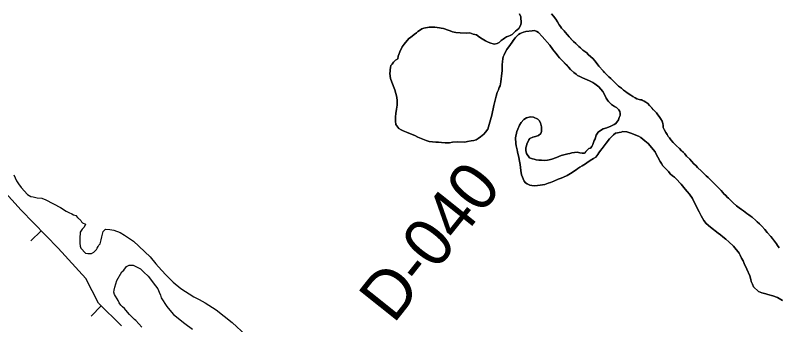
# Model space of a CAD drawing. Extents: x 3187622 to 3225504, y 800805 to 826213.
# Drawn here: x 3200621 to 3201935, y 813444 to 813977 of the extents above; entities that cross this region are included whole.
import ezdxf

# ---------------------------------------------------------------- set-up
doc = ezdxf.new("R2010")
doc.units = 0
for name, color, linetype in [('V-BORW-LINE', 7, 'Continuous'), ('V-RIVR-RANG-IDEN', 7, 'Continuous'), ('V-SITE-VEGE', 7, 'Continuous'), ('V-TOPO-SHOR', 7, 'Continuous')]:
    doc.layers.add(name, color=color, linetype=linetype)

msp = doc.modelspace()

# ---------------------------------------------------------------- linework, layer by layer
at = {"layer": 'V-BORW-LINE'}
for p, q in [((3200666.2, 813605.5), (3200648.2, 813588.1)), ((3200769.5, 813476.4), (3200751.9, 813458.6))]:
    msp.add_line(p, q, dxfattribs=at)
msp.add_lwpolyline([(3200804, 813442.2), (3200764.8, 813481), (3200742.7, 813523.6), (3200695, 813575.6), (3200631.7, 813641.3), (3200561.3, 813717.8), (3200477.3, 813821.7), (3200403.7, 813913.7), (3200338.8, 813979.6), (3200261.2, 814079.8), (3200192.3, 814157.6), (3200164.5, 814198.8), (3200123.2, 814226.2), (3200093.6, 814225.8), (3200067.7, 814233), (3200052.4, 814253), (3200045.7, 814270.2), (3200039.4, 814293.2), (3200029.7, 814306.3)], dxfattribs=at)
at = {"layer": 'V-SITE-VEGE'}
for points in [[(3201267.4, 813867.7), (3201266.5, 813871.7), (3201266.3, 813876.7), (3201266.4, 813879.7), (3201266.4, 813882.7), (3201267, 813886.9), (3201267.8, 813889.9), (3201269.9, 813892.4), (3201272.2, 813895.9), (3201276, 813899.3), (3201279.6, 813901.7), (3201280.7, 813906), (3201281.5, 813909.2), (3201283.1, 813913.9), (3201287.5, 813922.4), (3201290.6, 813927.1), (3201292.9, 813930), (3201296.5, 813934), (3201299, 813936.4), (3201301.6, 813938.6), (3201307.7, 813943.5), (3201312, 813946.4), (3201314.3, 813948.7), (3201316.9, 813950.6), (3201321.2, 813953.5), (3201324.4, 813954.7), (3201333.7, 813956), (3201343.5, 813955.9), (3201351.3, 813955.2), (3201354.5, 813954.6), (3201358.7, 813953.6), (3201366.4, 813950.9), (3201369.7, 813949.6), (3201374.2, 813948.2), (3201379.7, 813947.1), (3201387.4, 813946.5), (3201397.4, 813946), (3201403.7, 813946.2), (3201409.6, 813944.1), (3201415.1, 813942.9), (3201420.6, 813938.8), (3201424.8, 813936), (3201430.7, 813932.9), (3201434.4, 813930.8), (3201438.4, 813929), (3201445.4, 813927.1), (3201450.9, 813928), (3201454.2, 813929.7), (3201458, 813933.1), (3201461.1, 813935.3), (3201463.4, 813937.3), (3201466.9, 813939.7), (3201470.4, 813940.4), (3201473.2, 813941.6), (3201476.8, 813943.8), (3201482.6, 813949.2), (3201488, 813954.1), (3201490.8, 813958.8), (3201492.2, 813963), (3201491.4, 813974), (3201489.5, 813979.3)], [(3201544.1, 813979.3), (3201548, 813974.9), (3201551.7, 813970.1), (3201554.6, 813965.6), (3201557.5, 813960), (3201559.7, 813957.2), (3201561.6, 813954.6), (3201566, 813949.8), (3201568, 813947.3), (3201571.9, 813942.9), (3201574.6, 813939.4), (3201582.2, 813931.5), (3201586.2, 813927.9), (3201591.3, 813923), (3201594, 813920.7), (3201598.5, 813916.6), (3201601.9, 813914), (3201604.9, 813911.7), (3201607.6, 813909.2), (3201616, 813901.5), (3201619.2, 813898.2), (3201621.1, 813895.4), (3201625.7, 813889), (3201633.1, 813880.9), (3201639.2, 813874.5), (3201643.2, 813870.7), (3201646.4, 813867.9), (3201653.5, 813860.7), (3201659.9, 813854.8), (3201664.6, 813851), (3201668.3, 813847.6), (3201671.7, 813845.3), (3201674.7, 813843.3), (3201681.1, 813838.9), (3201684.1, 813836.8), (3201688.3, 813834.2), (3201691.5, 813832.7), (3201695.5, 813831.8), (3201699.8, 813830.7)], [(3201640.6, 813830.6), (3201638.7, 813833.7), (3201636.8, 813837.7), (3201632.7, 813845.3), (3201626, 813853.2), (3201619.1, 813858.4), (3201615.4, 813860.7), (3201609.5, 813863.8), (3201602, 813867), (3201597.6, 813869), (3201593.3, 813871.4), (3201589.1, 813873.2), (3201586.6, 813875), (3201582.9, 813878.1), (3201577.3, 813883.5), (3201573.6, 813887.5), (3201558.1, 813903.6), (3201555.5, 813906.9), (3201552.3, 813910.7), (3201548.6, 813915.3), (3201546.9, 813917.9), (3201541.5, 813925.2), (3201528.3, 813939.8), (3201521.7, 813946.7), (3201519.2, 813948.7), (3201515.2, 813950.3), (3201511.2, 813950.1), (3201500.2, 813948.6), (3201495.9, 813947.4), (3201490.3, 813945), (3201487.8, 813943.3), (3201485, 813941.1), (3201482.4, 813938.6), (3201480.6, 813935.9), (3201476.5, 813930.5), (3201473.9, 813926.5), (3201467.7, 813917.6), (3201464.6, 813912.4), (3201462.8, 813908.7), (3201461, 813905.2), (3201460.4, 813902.2), (3201460.1, 813896.7), (3201459.7, 813892), (3201459.3, 813881.7), (3201458.3, 813871.7), (3201457.8, 813867.2), (3201457.2, 813862), (3201456.3, 813858.5), (3201455.8, 813855.3), (3201454.5, 813852.3), (3201453.1, 813848.5), (3201451, 813843.6), (3201448.9, 813837.1), (3201447.5, 813830.4), (3201445.3, 813821.4), (3201444, 813815.4), (3201442.9, 813810.4), (3201441.8, 813804.7), (3201437.2, 813788.5), (3201434.8, 813780.8), (3201430.7, 813775.1), (3201428.1, 813772.1), (3201425.3, 813769.4), (3201422, 813767.5), (3201418.2, 813764.6), (3201414.7, 813762.4), (3201410.6, 813761.2), (3201406.3, 813760.3), (3201399.8, 813759.2), (3201395.3, 813758.2), (3201382.3, 813758.5), (3201374, 813758.1), (3201368.7, 813757.2), (3201361.5, 813757.1), (3201355.2, 813757.8), (3201350, 813758.4), (3201345.2, 813758.2), (3201333.7, 813759.4), (3201328.7, 813761), (3201322.8, 813763.4), (3201314.3, 813766.8), (3201309.3, 813769.4), (3201304.4, 813771.5), (3201294.9, 813775.2), (3201289.2, 813777.8), (3201285.7, 813779.4), (3201281.8, 813781.7), (3201279.6, 813783.8), (3201276.7, 813788.6), (3201276, 813794.1), (3201275.8, 813798.6), (3201275.9, 813801.9), (3201276.5, 813807.4), (3201277.4, 813815.1), (3201278.5, 813821.9), (3201278.7, 813829.6), (3201278.1, 813835.9), (3201276.4, 813841.7), (3201274.8, 813848), (3201269.8, 813861.3), (3201267.4, 813867.7)], [(3201589.8, 813712.7), (3201586.7, 813710.5), (3201577.3, 813704.1), (3201571.3, 813700.5), (3201564.9, 813697.9), (3201561.2, 813696.4), (3201555.9, 813694.5), (3201548.3, 813691.2), (3201542.7, 813688.8), (3201538.9, 813687.3), (3201532.6, 813685.5), (3201528.9, 813684.5), (3201524.6, 813683.9), (3201515.8, 813682.8), (3201510.6, 813683.4), (3201507.1, 813684.2), (3201502.4, 813686.3), (3201499.6, 813688.1), (3201497.4, 813690.9), (3201492.9, 813701.8), (3201491.5, 813709.3), (3201490.2, 813719.6), (3201489.1, 813725.6), (3201488, 813731.9), (3201485.9, 813741.5), (3201485, 813745.2), (3201483.6, 813751.8), (3201482.9, 813755.8), (3201482.6, 813765.6), (3201484.8, 813776.8), (3201486.4, 813780.8), (3201489.5, 813787.2), (3201491.9, 813791.9), (3201496.7, 813797.1), (3201501.5, 813799.8), (3201505.8, 813801.4), (3201508.8, 813801.6), (3201513.3, 813801.3), (3201520.8, 813797.9), (3201523.2, 813795.6), (3201525.7, 813791.3), (3201527.3, 813784.7), (3201527.4, 813776.7), (3201525.8, 813773), (3201522.2, 813769.8), (3201516.7, 813767.7), (3201512.2, 813766.7), (3201507.1, 813764.6), (3201505.1, 813762.1), (3201501.9, 813754.9), (3201501.1, 813751.9), (3201500, 813748.2), (3201500, 813743.9), (3201501.1, 813738.7), (3201506.7, 813731.3), (3201511.7, 813729.7), (3201514.7, 813728.6), (3201517.7, 813727.6), (3201522.4, 813727.2), (3201526.9, 813726.9), (3201532.2, 813726.5), (3201537.4, 813726.9), (3201540.5, 813727.9), (3201545, 813729), (3201553.1, 813731.9), (3201561.1, 813735), (3201565.7, 813736.4), (3201572.5, 813738), (3201576, 813738.7), (3201579.5, 813739.7), (3201588.3, 813740.7), (3201593.3, 813739.9), (3201597, 813739.1), (3201601.1, 813739.2), (3201606.2, 813745.1), (3201608.5, 813747.1), (3201611.5, 813748.1), (3201613.5, 813750.5), (3201615.4, 813754), (3201616.7, 813757.7), (3201618, 813760.9), (3201619.3, 813763.7), (3201621.2, 813770.4), (3201624.8, 813775.6), (3201628.6, 813778.5), (3201633.2, 813781.2), (3201639.7, 813783.1), (3201646.3, 813785.7), (3201652.4, 813788.6), (3201655.1, 813790.5), (3201659.8, 813796.5), (3201661.1, 813800.4), (3201662.4, 813804.2), (3201662.7, 813807.7), (3201662, 813810.7), (3201660.1, 813814), (3201656.4, 813817.6), (3201652.9, 813819.6), (3201647.5, 813823.2), (3201642.3, 813828.1), (3201640.6, 813830.6)], [(3201699.8, 813830.7), (3201704, 813828.7), (3201706.9, 813827.1), (3201710.2, 813824.5), (3201712.8, 813821.5), (3201722.4, 813811.5), (3201724.9, 813808.5), (3201727.6, 813805.2), (3201729.8, 813802.4), (3201732.2, 813798.8), (3201734.6, 813794.5), (3201736, 813790.2), (3201736.5, 813786.7), (3201736.7, 813783.2), (3201738.1, 813779.7), (3201741, 813774.9), (3201743.4, 813771.3), (3201745.4, 813768), (3201747.3, 813765.5), (3201749.8, 813762.4), (3201753.9, 813757.3), (3201757.1, 813754), (3201759.3, 813752), (3201764.5, 813747.3), (3201768.4, 813743.3), (3201773.6, 813737.9), (3201777, 813734.3), (3201782.2, 813728.7), (3201785.4, 813725.2), (3201789.5, 813720.8), (3201793.2, 813717.2), (3201795.7, 813714.7), (3201802.6, 813708), (3201807.5, 813703.2), (3201810.4, 813700.4), (3201813.9, 813697.3), (3201821.5, 813689.6), (3201826.2, 813685), (3201830.1, 813681.5), (3201836.2, 813674.8), (3201839.2, 813671.5), (3201841.1, 813669.2), (3201844.3, 813666.2), (3201846.5, 813663.6), (3201849, 813661.6), (3201857.1, 813653.6), (3201862.8, 813648.8), (3201867.2, 813645.2), (3201871.2, 813642.1), (3201874.6, 813640), (3201880.8, 813635.4), (3201884, 813633.1), (3201886.5, 813631.3), (3201889.5, 813629.2), (3201895.9, 813623.3), (3201898.6, 813621), (3201902.3, 813617.7), (3201906.2, 813613.4), (3201911.3, 813608), (3201915.5, 813602.9), (3201921.9, 813595.8), (3201931.7, 813583.1), (3201933.4, 813580.3), (3201936.3, 813576)], [(3201942, 813485.4), (3201933.1, 813490.9), (3201925.2, 813493.5), (3201916.9, 813495.7), (3201913.2, 813496.8), (3201906.2, 813498.9), (3201900.5, 813501.3), (3201891.9, 813509.2), (3201890.2, 813513.5), (3201888.3, 813518.3), (3201887.4, 813521.8), (3201885.5, 813527.9), (3201880.7, 813539.2), (3201875.9, 813549.3), (3201874, 813553.9), (3201871.6, 813558.2), (3201869.2, 813563.7), (3201867.5, 813567.3), (3201857.7, 813579), (3201849.8, 813586.7), (3201844.2, 813591.3), (3201839, 813595.4), (3201835.3, 813598.5), (3201831.3, 813601.5), (3201818.2, 813611.8), (3201810.4, 813618.2), (3201806.7, 813623.1), (3201802.1, 813631.4), (3201798.5, 813638), (3201794.8, 813644.6), (3201786.9, 813661), (3201781.8, 813668.6), (3201777.9, 813673.2), (3201774.4, 813677), (3201767.6, 813685.7), (3201758.3, 813695.6), (3201755.8, 813697.9), (3201752.6, 813700.2), (3201748.4, 813703.8), (3201745.7, 813707.4), (3201736.1, 813717.3), (3201733.5, 813721.4), (3201731.3, 813725), (3201727.4, 813732.3), (3201724.7, 813737.3), (3201722.6, 813741.6), (3201719.6, 813745.7), (3201714.3, 813752.1), (3201710.6, 813755.7), (3201705.2, 813760.5), (3201698.3, 813766.2), (3201694.3, 813768.2), (3201680.9, 813773.5), (3201674.1, 813775.9), (3201667.4, 813776.3), (3201664.1, 813775.6), (3201654.3, 813773.5), (3201651, 813770.8), (3201648.4, 813768.1), (3201644.4, 813763.7), (3201638.7, 813756.3), (3201631.3, 813747.2), (3201628.9, 813743.7), (3201626.1, 813740), (3201624.1, 813737), (3201620.7, 813732.6), (3201616.4, 813729.9), (3201613.6, 813728.5), (3201607.5, 813724.3), (3201602.7, 813720.9), (3201597.1, 813717.5), (3201593.1, 813715.1), (3201589.8, 813712.7)], [(3200618.8, 813701.8), (3200623.5, 813691.3), (3200627.1, 813686.4), (3200631.3, 813680.1), (3200642.7, 813668.3), (3200648.1, 813664.5), (3200652.4, 813663.8), (3200659.1, 813662.5), (3200667.1, 813661.7), (3200673.8, 813659.1), (3200699.2, 813645.7), (3200708.9, 813639.4), (3200713.8, 813636.9), (3200718.6, 813635), (3200721.7, 813633.1), (3200725.9, 813631.7), (3200728.3, 813628.6), (3200734.3, 813623), (3200735.5, 813621.1), (3200737.3, 813619.3), (3200742.2, 813616.7), (3200740.2, 813611.9), (3200736.5, 813608.3), (3200735.2, 813606.4), (3200733.3, 813603.4), (3200732.5, 813592.4), (3200732.4, 813584.4), (3200732.9, 813578.9), (3200734, 813575.8), (3200742.4, 813567.1), (3200746.1, 813566.4), (3200752.8, 813566.3), (3200756.6, 813568.7), (3200759.1, 813571.1), (3200761, 813573.5), (3200762.2, 813575.9), (3200764.1, 813578.3), (3200765.4, 813580.7), (3200767.3, 813583.2), (3200769.2, 813589.9), (3200770.6, 813595.3), (3200772.6, 813604.5), (3200776.9, 813608.1), (3200784.3, 813607.9), (3200791, 813606.6), (3200802, 813602.7), (3200809.2, 813598.3), (3200825, 813587.6), (3200853.8, 813560.6), (3200863.4, 813548.8), (3200873, 813537.6), (3200881.4, 813528.9), (3200893.4, 813517), (3200906.1, 813506.3), (3200928.5, 813491.8), (3200938.2, 813487.3), (3200948.5, 813481.6), (3200967.3, 813469.6), (3200995, 813447.6), (3201018.5, 813425.7)], [(3200839.2, 813439.8), (3200833.8, 813445.4), (3200829, 813451), (3200826.6, 813452.9), (3200818.2, 813461.7), (3200811.6, 813469.1), (3200809.2, 813471.6), (3200806.2, 813474.8), (3200803.2, 813477.3), (3200800.2, 813481.6), (3200798.4, 813485.3), (3200791.9, 813495.9), (3200790.8, 813499.6), (3200791.4, 813503.2), (3200792.8, 813508.7), (3200796, 813519.7), (3200804.9, 813534.8), (3200808, 813537.8), (3200813.1, 813543.9), (3200817.4, 813546.2), (3200824.1, 813546.1), (3200836.9, 813540.3), (3200842.9, 813534.1), (3200850.1, 813527.2), (3200862.7, 813511), (3200866.8, 813505.4), (3200869.2, 813499.9), (3200871.5, 813494.9), (3200872.7, 813490), (3200882.2, 813475.1), (3200884.6, 813472.6), (3200893.6, 813461.4), (3200913.5, 813445.7), (3200926.2, 813436.3)]]:
    msp.add_lwpolyline(points, dxfattribs=at)
at = {"layer": 'V-TOPO-SHOR'}
for points in [[(3201489.5, 813979.3), (3201491.4, 813974), (3201492.2, 813963), (3201490.8, 813958.8), (3201488, 813954.1), (3201482.6, 813949.2), (3201476.8, 813943.8), (3201473.2, 813941.6), (3201470.4, 813940.4), (3201466.9, 813939.7), (3201463.4, 813937.3), (3201461.1, 813935.3), (3201458, 813933.1), (3201454.2, 813929.7), (3201450.9, 813928), (3201445.4, 813927.1), (3201438.4, 813929), (3201434.4, 813930.8), (3201430.7, 813932.9), (3201424.8, 813936), (3201420.6, 813938.8), (3201415.1, 813942.9), (3201409.6, 813944.1), (3201403.7, 813946.2), (3201397.4, 813946), (3201387.4, 813946.5), (3201379.7, 813947.1), (3201374.2, 813948.2), (3201369.7, 813949.6)], [(3201616, 813901.5), (3201607.6, 813909.2), (3201604.9, 813911.7), (3201601.9, 813914), (3201598.5, 813916.6), (3201594, 813920.7), (3201591.3, 813923), (3201586.2, 813927.9), (3201582.2, 813931.5), (3201579.5, 813934.3), (3201574.6, 813939.4), (3201571.9, 813942.9), (3201568, 813947.3), (3201566, 813949.8), (3201561.6, 813954.6), (3201559.7, 813957.2), (3201557.5, 813960), (3201554.6, 813965.6), (3201551.7, 813970.1), (3201548, 813974.9), (3201544.1, 813979.3)], [(3201369.7, 813949.6), (3201366.4, 813950.9), (3201358.7, 813953.6), (3201354.5, 813954.6), (3201351.3, 813955.2), (3201343.5, 813955.9), (3201333.7, 813956), (3201324.4, 813954.7), (3201321.2, 813953.5), (3201316.9, 813950.6), (3201314.3, 813948.7), (3201312, 813946.4), (3201307.7, 813943.5), (3201301.6, 813938.6), (3201299, 813936.4), (3201296.5, 813934), (3201292.9, 813930), (3201290.6, 813927.1), (3201287.5, 813922.4), (3201283.1, 813913.9), (3201281.5, 813909.2), (3201280.7, 813906), (3201279.6, 813901.7), (3201276, 813899.3), (3201272.2, 813895.9), (3201269.9, 813892.4), (3201267.8, 813889.9), (3201267, 813886.9), (3201266.4, 813882.7), (3201266.4, 813879.7), (3201266.3, 813876.7), (3201266.5, 813871.7), (3201267.4, 813867.7), (3201269.8, 813861.3), (3201274.8, 813848), (3201276.4, 813841.7), (3201278.1, 813835.9), (3201278.7, 813829.6), (3201278.5, 813821.9), (3201277.4, 813815.1), (3201276.5, 813807.4), (3201275.9, 813801.9), (3201275.8, 813798.6), (3201276, 813794.1), (3201276.7, 813788.6), (3201279.6, 813783.8), (3201281.8, 813781.7), (3201285.7, 813779.4), (3201289.2, 813777.8), (3201294.9, 813775.2), (3201304.4, 813771.5), (3201309.3, 813769.4), (3201314.3, 813766.8), (3201322.8, 813763.4), (3201328.7, 813761), (3201333.7, 813759.4), (3201345.2, 813758.2), (3201350, 813758.4), (3201355.2, 813757.8), (3201361.5, 813757.1), (3201368.7, 813757.2), (3201374, 813758.1), (3201382.3, 813758.5), (3201395.3, 813758.2), (3201399.8, 813759.2), (3201406.3, 813760.3), (3201410.6, 813761.2), (3201414.7, 813762.4), (3201418.2, 813764.6), (3201422, 813767.5), (3201425.3, 813769.4), (3201428.1, 813772.1), (3201430.7, 813775.1), (3201434.8, 813780.8), (3201437.2, 813788.5), (3201441.8, 813804.7), (3201442.9, 813810.4), (3201444, 813815.4), (3201445.3, 813821.4), (3201447.5, 813830.4), (3201448.9, 813837.1), (3201451, 813843.6), (3201453.1, 813848.5), (3201454.5, 813852.3), (3201455.8, 813855.3), (3201456.3, 813858.5), (3201457.2, 813862), (3201457.8, 813867.2), (3201458.3, 813871.7), (3201459.3, 813881.7), (3201459.7, 813892), (3201460.1, 813896.7), (3201460.4, 813902.2), (3201461, 813905.2), (3201462.8, 813908.7), (3201464.6, 813912.4), (3201467.7, 813917.6), (3201473.9, 813926.5), (3201476.5, 813930.5), (3201478.6, 813933.2), (3201480.6, 813935.9)], [(3201480.6, 813935.9), (3201482.4, 813938.6), (3201485, 813941.1), (3201487.8, 813943.3), (3201490.3, 813945), (3201495.9, 813947.4), (3201500.2, 813948.6), (3201511.2, 813950.1), (3201515.2, 813950.3), (3201519.2, 813948.7), (3201521.7, 813946.7), (3201528.3, 813939.8), (3201541.5, 813925.2), (3201546.9, 813917.9), (3201548.6, 813915.3), (3201552.3, 813910.7), (3201555.5, 813906.9), (3201558.1, 813903.6), (3201566, 813895.5), (3201569.7, 813891.6), (3201573.6, 813887.5), (3201577.3, 813883.5), (3201582.9, 813878.1), (3201586.6, 813875), (3201589.1, 813873.2), (3201593.3, 813871.4), (3201597.6, 813869), (3201602, 813867), (3201609.5, 813863.8), (3201615.4, 813860.7), (3201619.1, 813858.4), (3201626, 813853.2), (3201632.7, 813845.3), (3201636.8, 813837.7), (3201638.7, 813833.7), (3201640.6, 813830.6), (3201642.3, 813828.1), (3201647.5, 813823.2), (3201653, 813819.6), (3201656.4, 813817.6), (3201660.1, 813814), (3201662, 813810.7), (3201662.7, 813807.7), (3201662.4, 813804.2), (3201661.1, 813800.4), (3201659.8, 813796.5), (3201655.1, 813790.5), (3201652.4, 813788.6), (3201646.3, 813785.7), (3201639.7, 813783.1), (3201633.2, 813781.2), (3201628.6, 813778.5), (3201624.8, 813775.6), (3201621.2, 813770.4), (3201619.3, 813763.7), (3201618, 813760.9), (3201616.7, 813757.7), (3201615.4, 813754), (3201613.5, 813750.5), (3201611.5, 813748.1), (3201608.5, 813747.1), (3201606.2, 813745.1), (3201603.6, 813742.2), (3201601.1, 813739.2), (3201597, 813739.1), (3201593.3, 813739.9), (3201588.3, 813740.7), (3201579.5, 813739.7), (3201576, 813738.7), (3201572.5, 813738), (3201565.7, 813736.4), (3201561.1, 813735), (3201553.1, 813731.9), (3201545, 813729), (3201540.5, 813727.9), (3201537.4, 813726.9), (3201532.2, 813726.5), (3201526.9, 813726.9), (3201522.4, 813727.2), (3201517.7, 813727.6), (3201514.7, 813728.6), (3201511.7, 813729.7), (3201506.7, 813731.3), (3201501.1, 813738.7), (3201500, 813743.9), (3201500, 813748.2), (3201501.1, 813751.9), (3201501.9, 813754.9), (3201505.1, 813762.1), (3201507.1, 813764.6), (3201512.2, 813766.7), (3201516.7, 813767.7), (3201522.2, 813769.8), (3201525.8, 813773), (3201527.4, 813776.7), (3201527.3, 813784.7), (3201525.7, 813791.3), (3201523.2, 813795.6), (3201520.8, 813797.9), (3201513.3, 813801.3), (3201508.8, 813801.6)], [(3201936.3, 813576), (3201933.4, 813580.3), (3201931.7, 813583.1), (3201924.8, 813592), (3201921.9, 813595.8), (3201915.5, 813602.9), (3201911.3, 813608), (3201906.2, 813613.4), (3201902.3, 813617.7), (3201898.6, 813621), (3201895.9, 813623.3), (3201889.5, 813629.2), (3201886.5, 813631.3), (3201884, 813633.1), (3201880.8, 813635.4), (3201874.6, 813640), (3201871.2, 813642.1), (3201867.2, 813645.2), (3201862.8, 813648.8), (3201857.1, 813653.6), (3201849, 813661.6), (3201846.5, 813663.6), (3201844.3, 813666.2), (3201841.1, 813669.2), (3201839.2, 813671.5), (3201836.2, 813674.8), (3201830.1, 813681.5), (3201826.2, 813685), (3201821.5, 813689.6), (3201813.9, 813697.3), (3201810.4, 813700.4), (3201807.5, 813703.2), (3201802.6, 813708), (3201795.7, 813714.7), (3201793.2, 813717.2), (3201789.5, 813720.8), (3201785.4, 813725.2), (3201782.2, 813728.7), (3201777, 813734.3), (3201773.6, 813737.9), (3201771.4, 813740.2), (3201768.4, 813743.3), (3201764.5, 813747.3), (3201759.3, 813752), (3201757.1, 813754), (3201753.9, 813757.3), (3201749.8, 813762.4), (3201747.3, 813765.5), (3201745.4, 813768), (3201743.4, 813771.3), (3201741, 813774.9), (3201738.1, 813779.7), (3201736.7, 813783.2), (3201736.5, 813786.7), (3201736, 813790.2), (3201734.6, 813794.5), (3201732.2, 813798.8), (3201729.8, 813802.4), (3201727.6, 813805.2), (3201724.9, 813808.5), (3201722.4, 813811.5), (3201720, 813814.1), (3201717, 813817.1), (3201712.8, 813821.5), (3201710.2, 813824.5), (3201706.9, 813827.1), (3201704, 813828.7), (3201699.8, 813830.8), (3201695.5, 813831.8), (3201691.5, 813832.7), (3201688.3, 813834.2), (3201684.1, 813836.8), (3201681.1, 813838.9), (3201674.7, 813843.3), (3201671.7, 813845.3), (3201668.3, 813847.6), (3201664.6, 813851), (3201659.9, 813854.8), (3201653.5, 813860.7), (3201646.4, 813867.9), (3201643.2, 813870.7), (3201639.2, 813874.5), (3201635.8, 813878.1), (3201633.1, 813880.9), (3201625.7, 813889), (3201621.1, 813895.4), (3201619.2, 813898.2), (3201616, 813901.5)], [(3201508.8, 813801.6), (3201505.8, 813801.4), (3201501.5, 813799.8), (3201496.7, 813797.1), (3201491.9, 813791.9), (3201489.5, 813787.2), (3201486.4, 813780.8), (3201484.8, 813776.8), (3201482.6, 813765.6), (3201482.9, 813755.8), (3201483.6, 813751.8), (3201485, 813745.2), (3201485.9, 813741.5), (3201488, 813731.9), (3201489.1, 813725.6), (3201490.2, 813719.6), (3201491.5, 813709.3), (3201492.9, 813701.8), (3201497.4, 813690.9), (3201499.6, 813688.1), (3201502.4, 813686.3), (3201507.1, 813684.2), (3201510.6, 813683.4), (3201515.8, 813682.8), (3201524.6, 813683.9), (3201528.9, 813684.5), (3201532.6, 813685.5), (3201538.9, 813687.3), (3201542.7, 813688.8), (3201548.3, 813691.2), (3201555.9, 813694.5), (3201561.2, 813696.4), (3201564.9, 813697.9), (3201571.3, 813700.5), (3201577.3, 813704.1), (3201586.7, 813710.5), (3201589.8, 813712.7), (3201593.1, 813715.1), (3201597.1, 813717.5), (3201602.7, 813720.9), (3201607.5, 813724.3), (3201613.6, 813728.5), (3201616.4, 813729.9), (3201620.7, 813732.6), (3201624.1, 813737), (3201626.1, 813740), (3201628.9, 813743.7), (3201631.3, 813747.2), (3201638.7, 813756.3), (3201644.4, 813763.7), (3201648.4, 813768.1), (3201651, 813770.8), (3201654.3, 813773.5), (3201664.1, 813775.6), (3201667.4, 813776.3), (3201674.1, 813775.9), (3201680.9, 813773.5), (3201694.3, 813768.2), (3201698.3, 813766.2), (3201701.7, 813763.3), (3201705.2, 813760.5), (3201710.6, 813755.7), (3201714.3, 813752.1), (3201719.6, 813745.7), (3201722.6, 813741.6), (3201724.7, 813737.3), (3201727.4, 813732.3), (3201731.3, 813725), (3201733.5, 813721.4), (3201736.1, 813717.3), (3201745.7, 813707.4), (3201748.4, 813703.8), (3201752.6, 813700.2), (3201755.8, 813697.9), (3201758.3, 813695.6), (3201767.6, 813685.7), (3201774.4, 813677), (3201777.9, 813673.2), (3201781.8, 813668.6), (3201786.9, 813661), (3201794.8, 813644.6), (3201798.5, 813638), (3201802.1, 813631.4), (3201806.7, 813623.1), (3201810.4, 813618.2), (3201818.2, 813611.8), (3201831.3, 813601.5), (3201835.3, 813598.5), (3201839, 813595.4), (3201844.2, 813591.3), (3201849.8, 813586.7), (3201857.7, 813579), (3201867.5, 813567.3), (3201869.2, 813563.7), (3201871.6, 813558.2), (3201874, 813553.9), (3201875.9, 813549.3), (3201880.7, 813539.2), (3201885.5, 813527.9), (3201887.4, 813521.8), (3201888.3, 813518.3)], [(3201888.3, 813518.3), (3201890.2, 813513.5), (3201891.9, 813509.2), (3201900.5, 813501.3), (3201906.2, 813498.9), (3201913.2, 813496.8), (3201916.9, 813495.7), (3201925.2, 813493.5), (3201933.1, 813490.9), (3201942, 813485.4)]]:
    msp.add_lwpolyline(points, dxfattribs=at)

# ---------------------------------------------------------------- texts
at = {"layer": 'V-RIVR-RANG-IDEN'}
msp.add_text('D-040', height=83, rotation=51.4272, dxfattribs=at).set_placement((3201272.4, 813444))

doc.saveas('drawing.dxf')
